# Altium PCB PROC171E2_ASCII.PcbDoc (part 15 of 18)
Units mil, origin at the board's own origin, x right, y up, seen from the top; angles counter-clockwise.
Board outline 7700 x 2300 mil, 6 copper layers (Top Layer, GND 1, SIG 1, SIG 2, GND 2, Bottom Layer), stack 61.062 mil thick; 938 components, 688 nets, 11933 pads, 1723 vias.
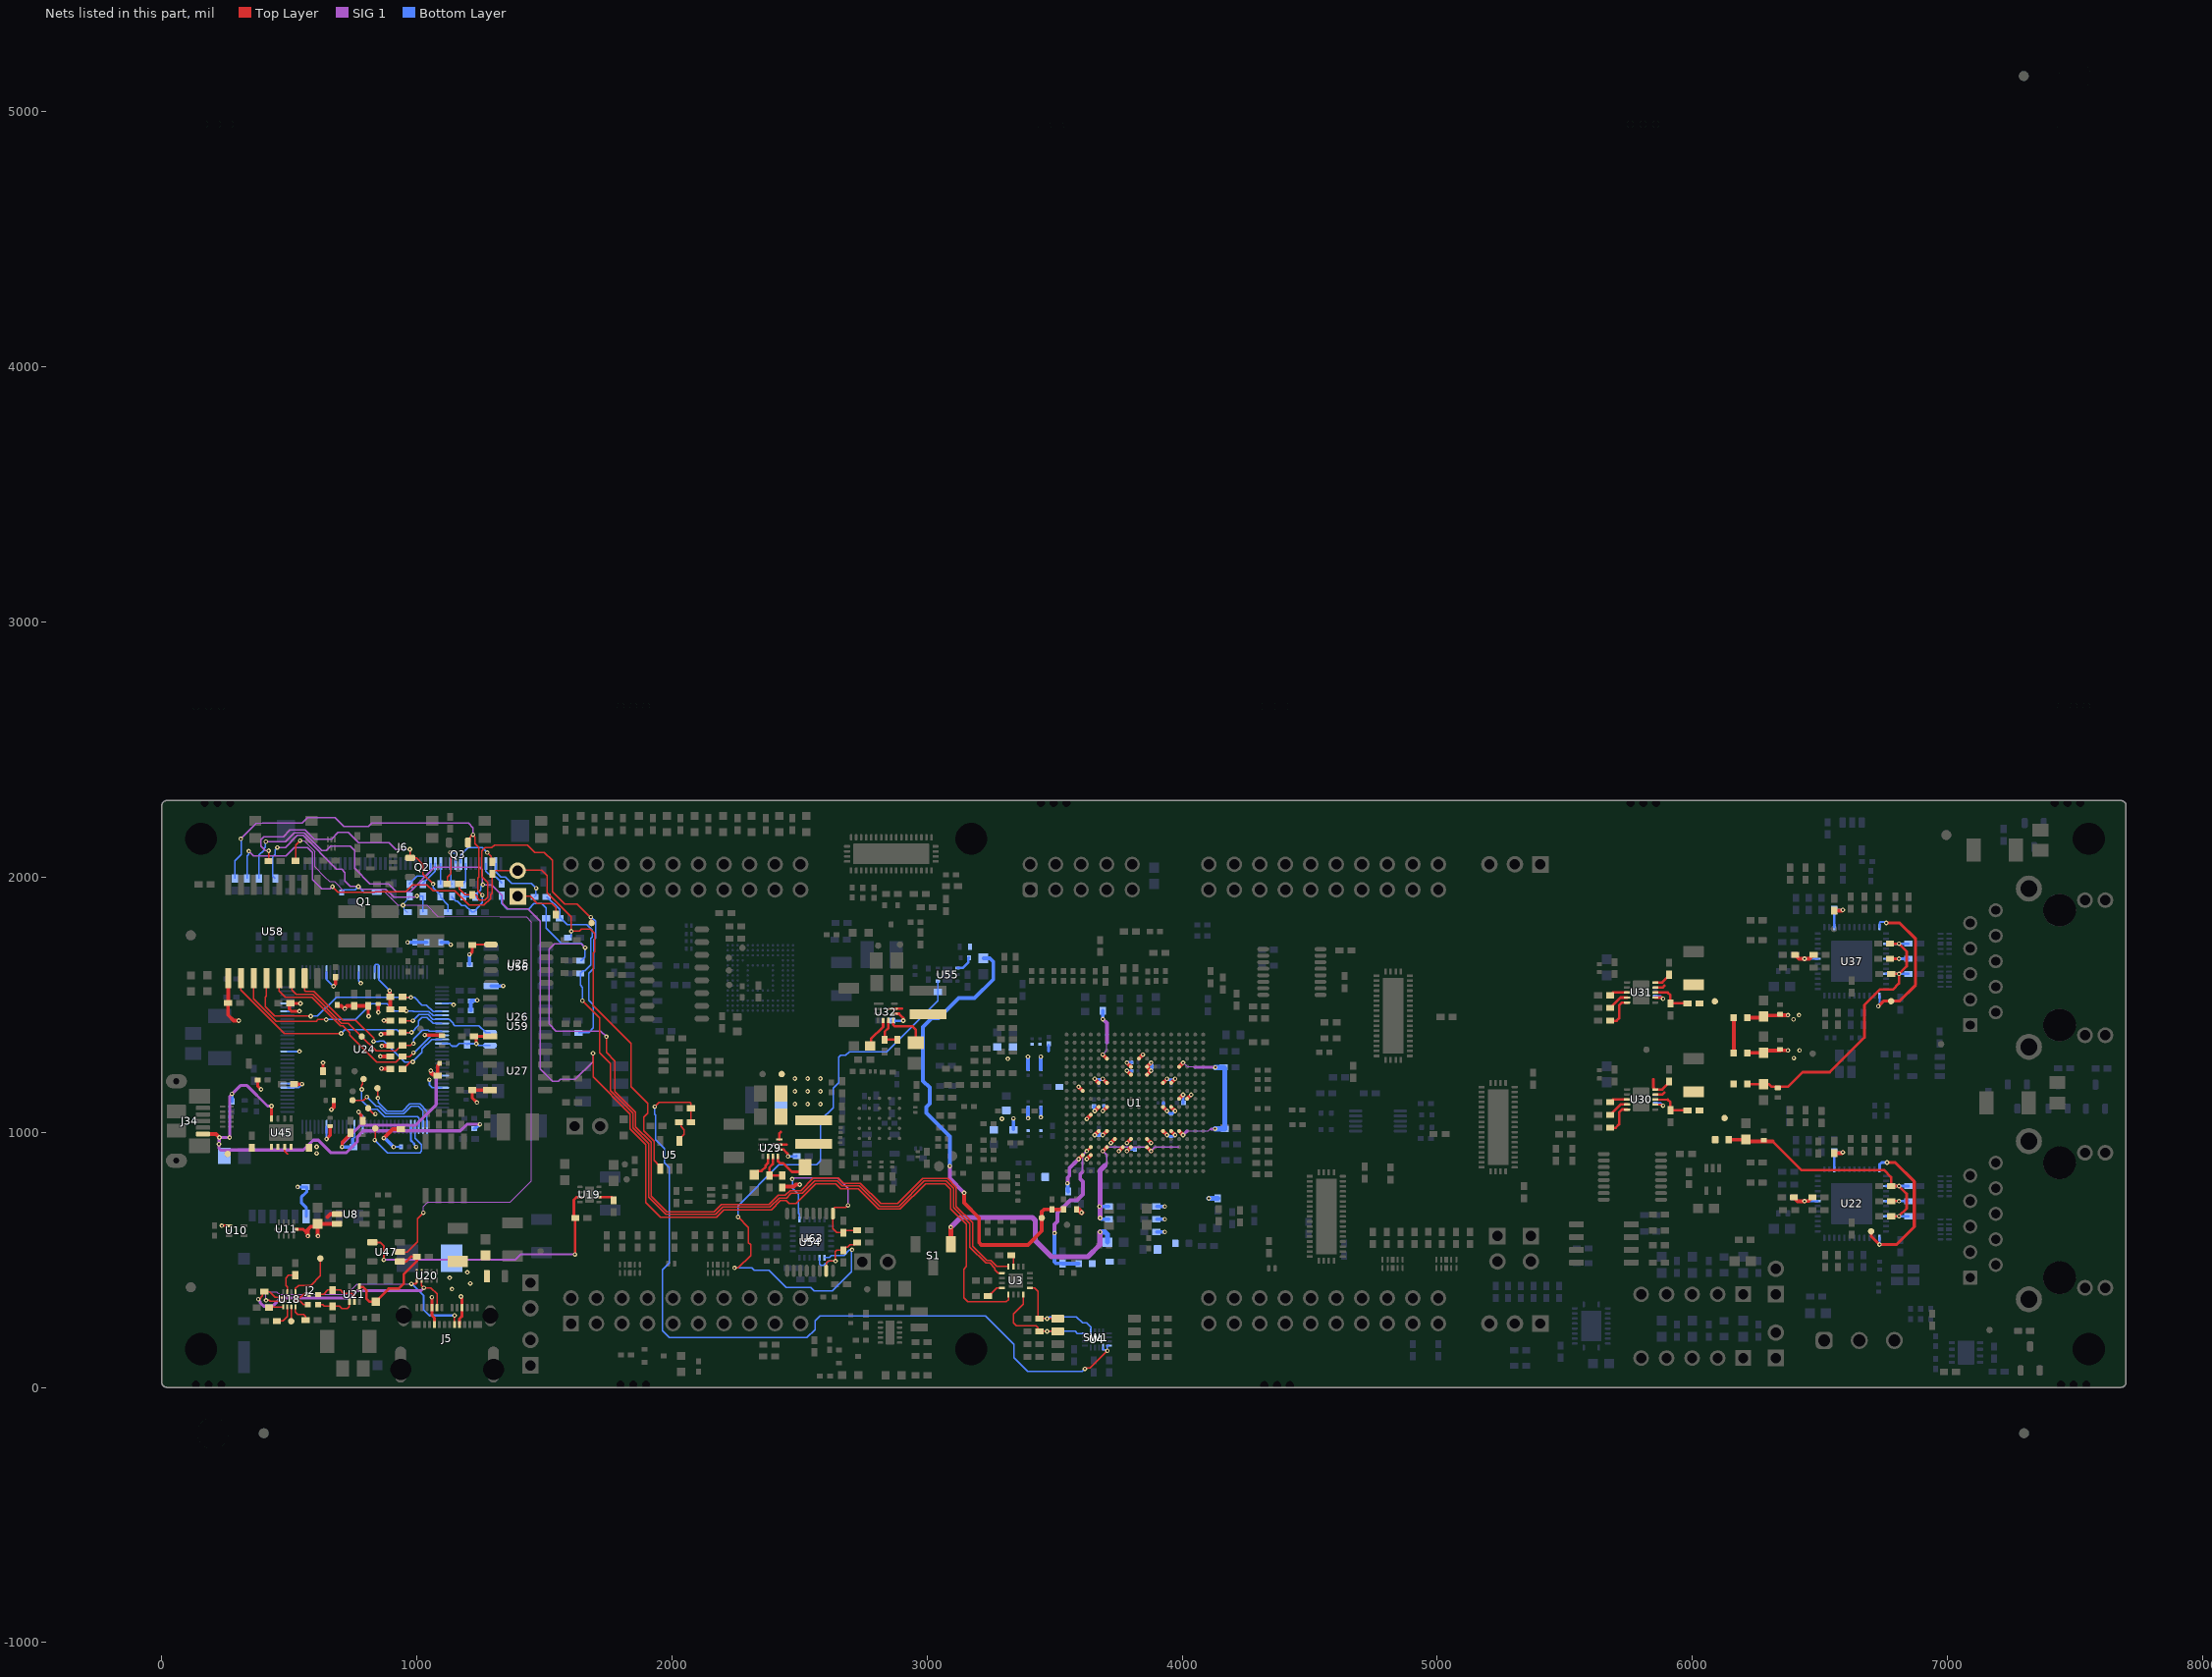
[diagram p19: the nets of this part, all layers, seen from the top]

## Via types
v1: diameter 18, hole 8, Top Layer to Bottom Layer, tented both sides, 1592 vias
v2: diameter 19.68, hole 7.87, Top Layer to Bottom Layer, tented both sides, 104 vias
v3: diameter 19.68, hole 7.87, Top Layer to Bottom Layer, 24 vias
v4: diameter 18, hole 8, Top Layer to Bottom Layer, 3 vias

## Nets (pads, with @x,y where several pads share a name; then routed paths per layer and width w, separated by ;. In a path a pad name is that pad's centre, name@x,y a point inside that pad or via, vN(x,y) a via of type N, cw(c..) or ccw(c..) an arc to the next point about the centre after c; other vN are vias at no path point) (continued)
SOP2_SW: R16.2 SW1.6 U3.4 U4.8 | length 476.2
  Top Layer w5.3: U3.4@3377.58,363.58 3377.58,327.08 3338.08,287.58 3338.08,252.82 3349.82,241.09 3353.63,241.09 3353.88,240.83 3370.06,240.83 3370.88,241.65 3427.87,241.65 3435.55,233.97 3435.55,219.51 v1(3470.3,219.51) SW1.6@3512.3,219.51
  Bottom Layer w5.3: v1(3470.3,219.51) 3581.42,219.51 3589.52,211.4 U4.8@3618.83,211.4
SOP3_SW: R17.2 SW1.5 U3.5 U4.9 | length 429.8
  Top Layer w5.3: U3.5@3403.17,389.17 3422,389.17 3435.55,375.62 3435.55,269.51 v1(3470.3,269.51) SW1.5@3512.3,269.51
  Bottom Layer w5.3: v1(3470.3,269.51) 3472.41,269.51 3479.75,276.85 3585.81,276.85 3610.21,252.45 3626.12,252.45 3642.45,236.12 U4.9@3642.45,219.28
SOP_DRIVE_OEN_R: R18.1 U5.4 | length 88.4
  Top Layer w5.3: U5.4@2028.71,965.53 2028.71,973.41 2047.77,992.46 2047.77,1010.18 2035.53,1022.42 2035.53,1034.66 R18.1@2031.05,1039.14
SOP_DRIVER_OEN: R18.2 R20.1 U4.1 U4.16 | length 3144.1
  Top Layer w5.3: v1(1932.26,1100.31) 1948.94,1116.99 2071.32,1116.99 2074.43,1113.89 R18.2@2074.43,1039.07 ; v1(3618.62,72.77) 3621.05,75.2 3638.62,75.2 v1(3706.65,143.24)
  Bottom Layer w5.3: v1(1932.26,1100.31) 1932.26,1070.44 1936.08,1066.62 1936.08,970.24 1970.28,936.04 1970.28,880.37 1989.78,860.87 1989.78,487.27 1963.14,460.63 1963.14,221.49 1990.23,194.4 2528.89,194.4 2561.1,226.61 2561.1,260.35 2580.86,280.11 3086.76,280.11 3086.8,280.15 3228.84,280.15 3340.56,168.43 3340.56,116.68 3395.19,62.05 3607.89,62.05 v1(3618.62,72.77) ; U4.1@3689.69,158.25 3689.69,148.41 3690.98,147.12 v1@3699.33,147.12 ; v1@3706.65,149.1 3706.65,162.87 3707.94,164.16 U4.16@3713.32,164.16
TA_GPIO1: Q3.1 R185.2 R342.2 R350.1 | length 1656.9
  Top Layer w5.3: Q3.1@1200.4,2131.24 1207.55,2138.4 1207.55,2156.55 1217,2166 v1(1220,2166) 1220,2164.37 1227.83,2156.55 1227.83,2130.72 1243.4,2115.15 1243.4,2000.59 1239.14,1996.33 1239.14,1947.32 v1(1257.17,1929.29)
  SIG 1 w5.3: v1(309.92,2150.15) 369.84,2210.07 395.43,2211.24 396.69,2211.3 396.91,2211.52 412.09,2211.52 ; 412.13,2211.52 538.8,2212.58 ; 538.85,2212.58 551,2212.58 572.42,2234 679,2234 713.7,2199.3 810.49,2199.3 822.82,2211.63 1201.87,2211.63 1220,2193.49 v1(1220,2166)
  Bottom Layer w5.3: R342.2@287,1994.62 287,2064 311,2088 v1@311,2149 ; R350.1@1138.11,1924.76 1138.11,1920.82 1152.93,1906 1158.27,1906 1160.43,1903.85 1174.97,1889.3 1189.9,1889.3 1216.26,1862.94 R185.2@1220.2,1862.94 1224.13,1862.94 1233.3,1872.1 1233.3,1876.04 1257.17,1899.91 v1(1257.17,1929.29)
TA_GPIO1_R: J6.30 R350.2 | length 83.6
  Bottom Layer w5.3: J6.30@1132.64,2053.35 1132.64,1977.47 R350.2@1138.11,1972
TA_GPIO1_XDS: R341.2 U24.74 U58.2 | length 997.1
  Top Layer w5.3: U58.2@310.25,1603.6 310.25,1557.91 480.85,1387.32 v1(703.3,1387.32) ; R341.2@943.31,1390.96 v1(979.22,1390.96)
  Bottom Layer w5.3: v1(703.3,1387.32) 718.75,1402.77 921.32,1402.77 933.13,1390.96 v1(979.22,1390.96) 1007.06,1418.8 1007.06,1437.32 1020,1450.26 1039.87,1450.26 1063.4,1426.73 U24.74@1098.65,1426.73
TA_GPIO2: R184.2 R351.1 R359.2 TP18.1 | length 1529
  Top Layer w5.3: R351.1@1166.36,1973.49 1166.36,1953.41 1189.34,1930.42 R184.2@1216.66,1930.42 1232.5,1930.42 1237.64,1925.28 1237.64,1917.62 1245.49,1909.77 1267.07,1909.77 1278.45,1921.14 1278.45,1978.55 1254,2003 1254,2101.61 1267.91,2115.52 1293.52,2115.52 1304,2126 1434,2126 1463,2097 1500,2097 1531,2066 1531,1943 1579.9,1894.1 1627.88,1894.1 1679.09,1842.89 v1(1681.82,1842.89) 1683.41,1841.29 1683.41,1821.59 TP18.1@1685,1820
  Bottom Layer w5.3: R359.2@1633.91,1389.97 1673.34,1389.97 1692.16,1408.79 1692.16,1437.84 1692.15,1500.55 1674.95,1517.75 1674.95,1623.27 1693.26,1641.58 1693.26,1754.66 1701,1762.4 1701,1826.2 1684.32,1842.89 v1(1681.82,1842.89)
TA_GPIO2_R: J6.31 R351.2 | length 192.6
  Top Layer w5.3: R351.2@1119.11,1973.49 1119.11,2000.89 1132.94,2014.72 1132.94,2095.06 v1(1131,2097)
  Bottom Layer w5.3: v1(1131,2097) 1133.43,2094.57 1149.77,2094.57 1152.87,2091.47 1152.87,2053.9 J6.31@1152.32,2053.35
TA_GPIO2_XDS: R301.2 U24.73 U59.2 | length 385.5
  Top Layer w5.3: R301.2@943.31,1437.81 944.33,1436.79 v1(984.31,1436.79)
  Bottom Layer w5.3: v1(984.31,1436.79) 1008.38,1460.86 1044.26,1460.86 1062.65,1442.48 U24.73@1098.65,1442.48 1099.14,1441.99 1127.95,1441.99 1142.66,1427.28 1142.66,1423.59 1148.55,1417.7 1243.5,1417.7 1271.2,1390 U59.2@1286.89,1390
TA_GPIO3: J1.2 R183.2 R343.2 R352.1 U5.1 | length 3033
  Top Layer w5.3: v1(669.14,1962.79) 669.86,1962.79 691.08,1941.58 834.88,1941.58 835.28,1941.98 956.39,1941.98 983.93,1969.52 1039.51,1969.52 1063.36,1945.67 1148.59,1945.67 1204,1890.25 1262.85,1890.25 1289.05,1916.45 1289.05,1931.74 1294.15,1936.85 1294.15,2010.53 R352.1@1296,2012.38 1296,2015.84 1305.16,2025 J1.2@1395.54,2025 ; J1.2@1398,2025 1400.3,2027.3 1488.7,2027.3 1510.7,2005.3 1510.7,1937.82 1604.02,1844.5 1604.02,1789.16 v1(1605.23,1787.95) ; v1@1604.76,1788.41 1637.55,1788.41 1645.13,1796 1680.12,1796 1696.34,1779.78 1696.34,1708.55 1690.74,1702.96 1690.74,1497.06 1839.67,1348.13 1839.67,1179.54 1906.02,1113.19 1906.02,1075.61 1889.8,1059.39 1889.8,1004.74 1929.68,964.87 1929.68,889.37 1953.91,865.14 U5.1@1953.91,857.27
  SIG 1 w5.3: v1(341,2102) 359.52,2083.48 486.48,2083.48 518.82,2115.82 571.75,2115.82 590.67,2096.9 590.67,1991.22 627.7,1954.18 659.31,1954.18 667.92,1962.79 v1(669.14,1962.79)
  Bottom Layer w5.3: R343.2@334.13,1994.62 334.13,2082.13 340.81,2088.81 340.81,2101.81 v1(341,2102) ; R183.2@1603.77,1765 1605.23,1766.46 v1(1605.23,1787.95)
TA_GPIO3_PD: J1.1 R21.2 | length 195.5
  Top Layer w5.3: J1.1@1395.54,1925 1444.27,1925 1473.05,1896.23 1529.94,1896.23 1545,1881.17 R21.2@1545,1853.25
TA_GPIO3_R: J6.32 R352.2 | length 201.6
  Top Layer w5.3: v1(1276,2096) 1291.78,2080.22 1291.78,2063.84 R352.2@1296,2059.62
  Bottom Layer w5.3: J6.32@1172.01,2053.35 1172.47,2053.81 1172.47,2086.47 1201.46,2115.46 1256.54,2115.46 v1(1276,2096)
TA_GPIO3_XDS: R340.2 U24.72 U58.3 | length 920.3
  Top Layer w5.3: U58.3@360.25,1603.6 360.25,1522.91 447.68,1435.48 605.4,1435.48 611.43,1441.5 v1(644.66,1441.5) ; R340.2@943.31,1481.93 951.93,1481.93 v1(958.55,1475.32)
  Bottom Layer w5.3: v1(644.66,1441.5) 760.46,1441.5 822.55,1503.59 884.17,1503.59 912.45,1475.32 v1(958.55,1475.32) 986.1,1475.32 987.65,1473.77 1047.7,1473.77 1063.24,1458.23 U24.72@1098.65,1458.23
TA_GPIO4: R182.2 R344.2 R354.1 U3.1 | length 5252
  Top Layer w5.3: v1(1690.74,1309.56) 1690.74,1216.22 1836.74,1070.21 1836.74,1012.83 1897.88,951.7 1897.88,724.83 1955.31,667.4 2174.55,667.4 2203.31,696.16 2389.14,696.16 2425.13,732.14 2448.04,732.14 2459.62,720.56 2485.61,720.56 2563.24,798.19 2642.28,798.19 2661.41,779.07 2730.19,779.07 2809.98,699.28 2895.07,699.28 2993.41,797.62 3071.26,797.62 3093.09,775.78 3093.09,700.37 3154.53,638.93 3154.53,473.86 3144.05,463.38 3144.05,351 3160.02,335.03 3310.03,335.03 3318.53,343.53 U3.1@3318.53,363.58
  SIG 1 w5.3: v1@410,2138 485,2138 520.53,2173.53 558.23,2173.53 627.58,2104.19 645.19,2104.19 662,2121 739.61,2121 756,2104.61 756,2034.1 815.83,1974.27 888.73,1974.27 920,1943 973,1943 1068.42,2038.42 1247.4,2038.42 1257.17,2028.65 1257.17,1971.95 v1(1258.92,1970.19) ; v1@1259.42,1970.19 1292.52,1970.19 1336.26,1926.46 1336.26,1895.72 1356.8,1875.17 1435.31,1875.17 1482.95,1827.52 1482.95,1248.59 1531.98,1199.56 1555.79,1199.56 1563.23,1207 1620.77,1207 1690.74,1276.97 v1(1690.74,1309.56)
  Bottom Layer w5.3: R344.2@381.31,1994.9 381.31,2086.31 399.48,2104.48 399.48,2111.09 406,2117.61 406,2137 v1(408,2139) ; R354.1@1182.29,1923.75 1228.05,1923.75 R182.2@1228.48,1923.32 1237.64,1932.48 1237.64,1937.95 1250.34,1950.65 1250.34,1961.61 v1(1258.92,1970.19)
TA_GPIO4_R: J6.33 R354.2 | length 86.2
  Bottom Layer w5.3: R354.2@1182.29,1971 1182.29,1974.93 1191.69,1984.34 J6.33@1191.69,2053.35
TA_GPIO4_XDS: R339.2 U24.71 U58.4 | length 908.9
  Top Layer w5.3: U58.4@410.25,1603.6 410.25,1534.58 405.26,1529.58 405.26,1492.89 443.15,1455 v1(584.18,1455) ; R339.2@943.31,1530.84 945.45,1528.69 v1(976.28,1528.69)
  Bottom Layer w5.3: v1(584.18,1455) 610.75,1455 684.44,1528.69 990.39,1528.69 1020.07,1499.02 1038.2,1499.02 1063.24,1473.98 U24.71@1098.65,1473.98
TA_I2C_SCL: R191.1 R356.1 R411.2 U3.12 | length 3748.3
  Top Layer w5.3: v1(1742.84,1374.31) 1742.84,1313.39 1776.91,1279.32 1776.91,1160.02 1857.94,1079 1857.94,1021.61 1919.08,960.48 1919.08,749.65 1980.13,688.6 2165.77,688.6 2194.53,717.36 2380.36,717.36 2416.35,753.34 2444.39,753.34 2462.45,771.41 2501.24,771.41 2505.35,771.41 2554,820.06 2652.61,820.06 2672.4,800.27 2738.97,800.27 2818.76,720.48 2883.63,720.48 2981.97,818.82 3080.04,818.82 3114.29,784.57 3114.29,709.15 3178.1,645.34 3178.1,554.05 3234.61,497.54 3250.35,497.54 3274.08,473.82 U3.12@3318.53,473.82
  SIG 1 w5.3: v1(1659.51,1723.8) 1644.52,1738.8 1539.94,1738.8 1517.66,1716.52 1517.66,1424.19 1545.3,1396.55 1720.59,1396.55 v1(1742.84,1374.31)
  Bottom Layer w5.3: R356.1@1331.93,1927.43 1331.93,1897.51 1353.49,1875.95 1438.86,1875.95 1459.13,1896.23 1490.16,1896.23 1507,1879.39 R191.1@1507,1838.89 1507,1800 1566.86,1740.14 1643.18,1740.14 v1(1659.51,1723.8) 1659.51,1686.92 1645.43,1672.84 R411.2@1641.49,1672.84
TA_I2C_SCL_R: J6.37 R356.2 | length 113.4
  Bottom Layer w5.3: J6.37@1270.43,2053.35 1270.43,2024.27 1294.23,2000.47 1310.07,2000.47 1331.93,1978.61 R356.2@1331.93,1974.68
TA_I2C_SDA: R192.1 R358.1 R409.2 U3.13 | length 3235.8
  Top Layer w5.3: v1(1649.12,1515.38) 1716.8,1447.7 1716.8,1311.11 1759.04,1268.88 1759.04,1162.91 1847.34,1074.61 1847.34,1017.22 1908.48,956.09 1908.48,745.26 1975.74,678 2170.16,678 2198.92,706.76 2384.75,706.76 2420.74,742.74 2448.78,742.74 2463.04,757.01 2466.84,760.81 2510.87,760.81 2559.52,809.46 2647.76,809.46 2667.55,789.67 2734.58,789.67 2814.37,709.88 2890.68,709.88 2989.02,808.22 3075.65,808.22 3103.69,780.17 3103.69,704.76 3167.5,640.94 3167.5,549.66 3230.22,486.94 3245.96,486.94 3266.36,466.54 3266.36,460.34 3278.47,448.23 U3.13@3292.94,448.23
  Bottom Layer w5.3: R358.1@1509.01,1923.75 1559.77,1873 R192.1@1559.77,1838.79 1563.7,1838.79 1588.88,1813.62 1666.93,1813.62 1688.52,1792.03 1688.52,1764.91 1682.66,1759.05 1682.66,1655.31 1659.25,1631.89 1650.19,1631.89 R409.2@1641.03,1622.73 1641.03,1576.31 1649.12,1568.22 v1(1649.12,1515.38)
TA_I2C_SDA_R: J6.39 R358.2 | length 252.3
  Bottom Layer w5.3: J6.39@1309.8,2053.35 1309.8,2020.08 1329.41,2000.47 1347.91,2000.47 1372.89,1975.5 1449.08,1975.5 v1@1466.29,1958.29 ; R358.2@1461.38,1923 1466,1927.62 v1@1466,1958
  other v1: 1468.12,1956.46
TA_PORZ: Q1.1 R180.1 R187.2 R345.2 R347.1 | length 1067.8
  SIG 1 w5.3: v1@454,2115 484,2115 531.93,2162.93 553.84,2162.93 685.77,2031 705.7,2031 718.24,2018.47 718.24,1984.67 739.91,1963 v1(771,1963) 780.93,1953.07 877.93,1953.07 910,1921 991.91,1921 996.99,1926.07 v1(1000.42,1926.07)
  Bottom Layer w5.3: R345.2@445,1994.62 435.84,2003.78 435.84,2009.99 435,2010.82 435,2080.39 444,2089.39 444,2106.55 453,2115.55 v1(453,2116) ; R180.1@706,1940.32 706,1942.28 713.19,1949.48 757.48,1949.48 v1(771,1963) 792.48,1941.52 Q1.1@842.87,1941.52 ; R180.1@706.82,1937.79 R180.1@706.82,1939.76 ; v1(1000.42,1926.07) 1003.62,1926.07 1006.59,1923.11 1008.24,1924.76 R347.1@1024.02,1924.76 1024.02,1864.97 R187.2@1026.05,1862.94
TA_PORZ_R: J6.27 R347.2 | length 101.9
  Bottom Layer w5.3: R347.2@1024.02,1972 1024.02,1975.94 1072.01,2023.93 1072.01,2051.77 J6.27@1073.58,2053.35
TA_PORZn_XDS: R338.2 U24.77 U58.5 | length 852.1
  Top Layer w5.3: U58.5@460.25,1603.6 460.25,1554.54 485.54,1529.25 588.68,1529.25 700.83,1417.11 709.49,1417.11 736.59,1390.01 736.59,1381.08 842.97,1274.7 917.51,1274.7 939.37,1296.56 R338.2@943.31,1296.56 971.67,1296.56 986.6,1311.49 v1(986.6,1311.61)
  Bottom Layer w5.3: v1(986.6,1311.61) 989.67,1311.61 1057.05,1379 1098.16,1379 U24.77@1098.65,1379.49
TA_POWERDOWNZ: R188.2 R346.1 R353.2 U47.2 | length 2953.3
  Top Layer w5.3: R353.2@524.76,2064 524.76,2125.76 v1@541.85,2142.85 ; U47.2@933.63,531 962.79,531 1002.6,570.81 1002.6,661.18 v1(1025.82,684.4)
  SIG 1 w4.75: v1@541.91,2143.41 v1(542.32,2143) v1@543,2143 ; v1@543,2143.41 558.76,2143.41 600.99,2101.18 600.99,2041.05 637.7,2003 658.05,1982.65 676.5,1982.65 716.41,1942.74 873.26,1942.74 926.25,1889.75 v1(945.6,1889.75) ; v1@948.76,1889.75 1039.1,1889.75 1082.45,1846.39 1326.11,1843.51 ccw(c1326.34,1862.76) 1326.59,1843.51 1424.3,1845 1428.24,1845 1429.63,1843.61 1449.33,1823.91 1449.33,1121.99 ; v1(1025.82,684.4) 1025.82,708.65 1043,725.82 1366.23,725.82 1449.32,808.92 1449.32,1121.98
  Bottom Layer w4.75: R188.2@963.89,1862.94 959.96,1862.94 950.52,1872.37 950.52,1881.24 945.6,1886.16 v1(945.6,1889.75) 948.14,1892.29 948.14,1897.22 971.74,1920.82 R346.1@971.74,1924.76
TA_POWERDOWNZ_R: J6.26 R346.2 | length 136
  Bottom Layer w5.3: R346.2@971.74,1972 971.74,1975.94 999.94,2004.14 1035.15,2004.14 1053.9,2022.88 J6.26@1053.9,2053.35
TA_PWRDNz_XDS: R336.2 U24.78 U58.7 | length 810.5
  Top Layer w5.3: U58.7@560.25,1603.6 560.25,1554.96 563.36,1551.86 596.06,1551.86 709.61,1438.31 760.87,1438.31 830.55,1368.63 v1(830.55,1356.24) ; R336.2@943.31,1248.06 947.24,1248.06 975.17,1275.98 984.23,1275.98 v1(984.54,1275.67)
  Bottom Layer w5.3: v1(830.55,1356.24) 831.96,1354.83 850.15,1354.83 853.03,1357.71 870.6,1357.71 952.65,1275.67 v1(984.54,1275.67) ; v1(984.54,1275.67) 984.51,1278.25 1019.82,1313.56 1019.82,1325.87 1057.69,1363.74 U24.78@1098.65,1363.74
TA_RESETZ: Q2.1 R186.2 R348.1 R349.2 | length 1076.7
  Top Layer w5.3: R349.2@418.76,2063 418.76,2102.76 v1(419,2103) ; v1(973,2109) 973.76,2108.24 Q2.1@973.76,2075.4 ; Q2.1@975,2075 999,2075 1024.64,2049.36 1024.64,2012 v1(1063.57,1973.07)
  SIG 1 w5.3: v1(419,2103) 418.31,2103.69 406.31,2103.69 388.48,2121.52 388.48,2147.09 399.91,2158.52 477.52,2158.52 503.13,2184.13 562.62,2184.13 597.75,2149 664.95,2149 690.47,2174.52 731.48,2174.52 771,2135 891,2135 917,2109 v1(973,2109)
  Bottom Layer w5.3: v1(1063.57,1973.07) 1063.57,1957.38 1092.26,1928.7 R348.1@1092.26,1924.76 1092.26,1920.82 1121.59,1891.49 R186.2@1121.59,1862.94
TA_RESETZ_R: J6.28 R348.2 | length 81.8
  Bottom Layer w5.3: R348.2@1092.26,1972 1093.27,1973.01 J6.28@1093.27,2053.35
TA_RESETz_XDS: R337.2 TP32.1 U24.76 U58.6 | length 779.8
  Top Layer w5.3: U58.6@510.25,1603.6 510.25,1557.01 527.42,1539.85 593.07,1539.85 705.22,1427.71 731.47,1427.71 TP32.1@784.17,1375 840.51,1318.67 917.51,1318.67 939.37,1340.53 R337.2@943.31,1340.53 976.2,1340.53 983.28,1347.61 v1(986.59,1347.61)
  Bottom Layer w5.3: v1(986.59,1347.61) 986.59,1364.76 1022.23,1400.4 1044.54,1400.4 1049.71,1395.24 U24.76@1098.65,1395.24
TCA_ADDR: R10.2 U3.16 | length 67
  Top Layer w5.3: R10.2@3238.62,358.58 3247.78,367.74 3252.17,367.74 3273.6,389.17 U3.16@3292.94,389.17
TCA_INTN: R11.2 U3.11 | length 46.5
  Top Layer w5.3: R11.2@3330.46,517.07 3338.21,509.32 U3.11@3338.21,473.82
TM4C129_TCK: TP27.1 U24.100 | length 359.1
  Top Layer w5.3: v1(834.93,969.22) 836.15,970.44 836.15,1013.78 TP27.1@837.37,1015
  Bottom Layer w5.3: v1(834.93,969.22) 884.44,919.71 1011.99,919.71 1018.05,925.76 1018.05,950.75 992.31,976.49 992.31,1021.18 U24.100@992.35,1021.22
TM4C129_TDI: TP29.1 U24.98 | length 389.7
  Top Layer w5.3: TP29.1@747.83,1125.66 791.27,1125.66 v1(803.8,1138.19)
  Bottom Layer w5.3: v1(803.8,1138.19) 840.65,1101.33 849.78,1101.33 878.6,1072.51 948.54,1072.51 976.75,1100.72 1007,1100.72 1023.85,1083.87 U24.98@1023.85,1021.22
TM4C129_TDO: TP30.1 U24.97 | length 347
  Top Layer w5.3: TP30.1@845.57,1172.78 846.44,1171.91 846.44,1135.02 v1(847.31,1134.15)
  Bottom Layer w5.3: v1(847.31,1134.15) 848.91,1132.55 848.91,1117.2 882.99,1083.11 944.15,1083.11 972.36,1111.32 1011.39,1111.32 1039.59,1083.11 U24.97@1039.59,1021.22
TM4C129_TMS: TP28.1 U24.99 | length 373
  Top Layer w5.3: v1(784.17,1168.37) 784.17,1185.32 787.4,1188.54 787.4,1204.77 TP28.1@791.17,1208.54
  Bottom Layer w5.3: v1(784.17,1168.37) 784.17,1125.66 819.11,1090.73 845.39,1090.73 856.83,1079.29 874.45,1061.67 1001.81,1061.67 1008.1,1055.38 U24.99@1008.1,1021.22
TPS62913_1_EN_SYNC: R146.1 U29.1 | length 85.6
  Top Layer w10: U29.1@2420.33,931.84 2438.13,931.84 2453.47,916.5 2453.47,906.8 v1(2455,905.27)
  Bottom Layer w10: v1(2455,905.27) 2455.71,905.98 2488,905.98 R146.1@2488.71,906.68
TPS62913_1_FB: R153.1 R154.2 U29.9 | length 130.5
  Top Layer w10: U29.9@2395.73,905.26 2395.73,874.96 2382.33,861.57 R154.2@2382.33,830.3 R153.1@2432.33,830.3
TPS62913_1_NR_SS: C160.1 U29.8 | length 102.5
  Top Layer w10: C160.1@2322.84,833.18 2322.84,834.16 2336.54,847.86 2350.85,847.86 2367.03,864.05 2367.03,870.42 2376.04,879.44 U29.8@2376.04,905.26
TPS62913_1_SCONF: R148.2 U29.10 | length 127.9
  Top Layer w10: U29.10@2415.41,905.26 2415.41,886.62 2423.84,878.19 2436.49,878.19 2470,844.68 R148.2@2507.33,844.68
TPS62913_1_SW: L2.1 U29.2 | length 36.6
  Top Layer w10: U29.2@2413.45,951.52 2450,951.52
TPS62913_2_EN_SYNC: R156.1 U32.1 | length 95.8
  Top Layer w10: U32.1@2872.01,1464.46 2889.83,1464.46 2906.67,1447.62 v1(2906.67,1437.62)
  Bottom Layer w10: R156.1@2861.31,1436.47 v1@2905.52,1436.47
TPS62913_2_FB: R162.1 R163.2 U32.9 | length 130.5
  Top Layer w10: U32.9@2847.4,1437.88 2847.4,1407.58 2834,1394.19 R163.2@2834,1362.92 R162.1@2884,1362.92
TPS62913_2_NR_SS: C177.1 U32.8 | length 121
  Top Layer w10: C177.1@2776.59,1338.05 2780.43,1341.89 2780.43,1365.89 2827.72,1413.18 U32.8@2827.72,1437.88
TPS62913_2_SCONF: R160.2 U32.10 | length 164.5
  Top Layer w10: U32.10@2867.09,1437.88 2867.09,1422.06 2874.55,1414.59 2943.56,1414.59 2956.47,1401.68 R160.2@2956.47,1350.85
TPS62913_2_SW: L3.1 U32.2 | length 36.6
  Top Layer w10: U32.2@2865.12,1484.14 2901.67,1484.14
TPS74801_1_BIAS: R150.2 U30.4 | length 83.3
  Top Layer w10: R150.2@5677.75,1067.63 5718.86,1108.75 U30.4@5744.01,1108.75
TPS74801_1_EN: R149.2 U30.5 | length 123.2
  Top Layer w10: R149.2@5677.75,1017.63 5699.82,1017.63 5712.84,1030.65 5712.84,1077.3 5724.6,1089.06 U30.5@5744.01,1089.06
TPS74801_1_FB: R151.1 R152.2 U30.8 | length 162.4
  Top Layer w8: U30.8@5854.25,1128.43 5903.33,1128.43
  Top Layer w10: 5903.33,1128.43 5914.13,1117.63 R152.2@5914.13,1085.98 R151.1@5980.51,1085.98
TPS74801_1_PG: R147.1 U30.3 | length 70.7
  Top Layer w10: R147.1@5677.75,1117.63 5688.55,1128.43 U30.3@5744.01,1128.43
TPS74801_1_SS: C166.2 U30.7 | length 68.3
  Top Layer w8: U30.7@5854.25,1108.75 5877.91,1108.75 v1@5883.57,1103.09
  Top Layer w10: v1@5882.84,1103.83 v1(5885,1103.83)
  Bottom Layer w10: C166.2@5854.25,1112.69 5875.45,1112.69 5884.3,1103.83 v1(5885,1103.83)
TPS74801_2_BIAS: R158.2 U31.4 | length 83.3
  Top Layer w10: R158.2@5677.75,1486.82 5718.86,1527.94 U31.4@5744.01,1527.94
TPS74801_2_EN: R157.2 U31.5 | length 125.2
  Top Layer w10: R157.2@5677.75,1436.82 5703.29,1436.82 5712.84,1446.37 5712.84,1496.49 5724.6,1508.25 U31.5@5744.01,1508.25
TPS74801_2_FB: R159.1 R161.2 U31.8 | length 162.4
  Top Layer w10: U31.8@5854.25,1547.62 5903.33,1547.62 5914.13,1536.82 R161.2@5914.13,1505.17 R159.1@5980.51,1505.17
TPS74801_2_PG: R155.1 U31.3 | length 70.7
  Top Layer w10: R155.1@5677.75,1536.82 5688.55,1547.62 U31.3@5744.01,1547.62
TPS74801_2_SS: C178.2 U31.7 | length 67.2
  Top Layer w10: U31.7@5854.25,1527.94 5880.08,1527.94 v1(5885,1523.02)
  Bottom Layer w10: C178.2@5854.25,1531.87 5875.45,1531.87 5884.3,1523.02 v1(5885,1523.02)
TPS_CT: C109.1 U19.6 | length 64.7
  Top Layer w10: U19.6@1714.33,746.06 1763.07,746.06 1771.58,737.56 C109.1@1771.58,733.62
TPS_VSYS_5V0_ON: R98.1 U19.3 U47.4 | length 1108.3
  Top Layer w8: U47.4@825.37,568.4 856.6,568.4 870,555 v1(870,499.73)
  Top Layer w10: v1(1620,520.76) 1620,664.65 1615.61,669.04 1615.61,734.29 1627.39,746.06 U19.3@1639.52,746.06
  SIG 1 w8: v1(870,499.73) 1384.73,499.73 1405.76,520.76 v1(1620,520.76)
TUSB_ADDR: TP5.1 U18.5 | length 56.5
  Top Layer w5.3: TP5.1@507.51,259.31 508.07,259.87 U18.5@508.07,315.56
TUSB_EN_N: R97.2 U18.11 | length 98.2
  Top Layer w5.3: U18.11@492.32,374.61 492.24,374.69 492.24,393.2 486.21,399.23 486.21,428.62 497.39,439.79 R97.2@523.29,439.79
TUSB_ID: TP3.1 U18.9 | length 199.6
  Top Layer w5.3: U18.9@523.82,374.61 523.9,374.69 523.9,387.72 536.18,400 584.4,400 621.55,437.15 TP3.1@621.55,505.45
TUSB_OUT: DS4.1 R299.1 U21.4 U47.1 | length 447.5
  Top Layer w10: U21.4@774.98,394.13 788.32,394.13 801.98,380.48 801.98,347.94 814.26,335.65 DS4.1@838.68,335.65 890.03,387 929,387 948,406 948,442.5 999.88,494.38 R299.1@999.88,512.5 977.5,512.5 958.6,493.6 U47.1@933.63,493.6
TUSB_OUT1: R89.2 R93.2 U21.1 | length 152.9
  Top Layer w5.3: R89.2@612.51,324.31 630.69,324.31 637.07,317.93 R93.2@669.95,317.93 696.07,317.93 705.97,308.03 727.47,308.03 735.61,316.17 U21.1@735.61,335.87
TUSB_OUT1_R: R89.1 U18.7 | length 52.7
  Top Layer w5.3: U18.7@525.79,337.21 543.62,337.21 556.48,324.35 R89.1@573.14,324.31 R89.1@573.14,324.31
TUSB_OUT2: R90.2 R92.2 U21.2 | length 181.4
  Top Layer w5.3: R90.2@612.51,364.41 634.16,364.41 650.82,381.07 R92.2@669.95,381.07 700,381.07 712.8,368.26 745,368.26 755.3,357.97 U21.2@755.3,335.87
TUSB_OUT2_R: R90.1 U18.8 | length 52.1
  Top Layer w5.3: U18.8@525.79,352.96 544.38,352.96 555.83,364.41 R90.1@573.14,364.41
TUSB_OUT3: R91.1 U18.6 | length 81.7
  Top Layer w5.3: U18.6@523.82,315.56 523.82,295 533.82,285 556.48,285 563.88,277.6 R91.1@563.88,263.69
TUSB_PORT: R95.2 U18.3 | length 57.8
  Top Layer w5.3: R95.2@420.03,312.6 422.98,315.56 U18.3@476.58,315.56
TUSB_VBUS_DET: R94.1 U18.4 | length 86.2
  Top Layer w5.3: R94.1@451.47,260.08 475.08,260.08 492.32,277.32 U18.4@492.32,315.56
UART/EPWM_MUX_EN: R396.1 R398.2 U54.15 U63.14 | length 304.1
  Top Layer w5.3: U54.15@2605.18,457 2605.18,487.19 2613.22,495.22 v1(2641.13,495.22) 2641.13,533 2645.36,537.23 R398.2@2671.47,537.23 2671.47,539.76 2680.63,548.92 2687.98,548.92 2697.94,558.87 2716.98,558.87 R396.1@2725.68,567.58
  Bottom Layer w5.3: U63.14@2578.49,508.67 2578.49,484.23 2584.41,478.31 2593.55,478.31 2602.04,486.81 2605.9,486.81 2614.32,495.22 v1(2641.13,495.22)
UART/EPWM_MUX_SEL: R395.1 R397.2 U54.1 U63.1 | length 724.9
  Top Layer w5.3: v1(2690.18,713.16) 2688.7,713.16 2680.72,705.18 2639.1,705.18 2632.77,698.85 2632.77,683.41 U54.1@2630.77,681.41 2630.77,621.86 2646.33,606.3 R397.2@2671.47,606.3 2680.34,615.17 R395.1@2725.69,615.17 R395.1@2729.62,615.17
  SIG 1 w5.3: v1(2471.32,816.48) 2474.76,816.48 2479.48,821.2 2649.19,821.2 2690.18,780.2 v1(2690.18,713.16)
  Bottom Layer w5.3: v1(2471.32,816.48) 2471.32,815.22 2472.96,813.58 2472.96,780.29 2496.72,756.53 2496.72,681.46 2499.75,678.43 U63.1@2499.75,658.28
USBTYPEC_CC1: J5.A5 R439.2 U18.1 U20.4 U20.7 | length 997.4
  Top Layer w5.3: v1(378.93,345.42) 382.33,345.42 394.87,357.96 394.87,366.96 R439.2@402.52,374.61 423.19,374.61 444.85,352.96 U18.1@474.61,352.96 ; U20.4@1018.85,453.43 U20.7@1018.85,420.56 1018.85,399.45 1027.76,390.54 v1(1027.76,390) 1055,390 1079.12,365.88 1079.12,312.74 J5.A5@1078.98,312.6
  SIG 1 w12: v1(378.93,345.42) 378.93,343.79 385.78,336.95 385.78,331.81 399.18,318.42 434.72,318.42 466.95,350.65 736.61,350.65 765.01,379.05 1016.82,379.05 v1(1027.76,390)
USBTYPEC_CC2: J5.B5 U18.2 U20.5 U20.6 | length 1045.9
  Top Layer w5.3: v1(408.65,341.29) 408.7,341.24 421.97,341.24 425.99,337.21 U18.2@474.61,337.21 ; J5.B5@1147.87,245.67 v1(1147.87,281.86)
  Top Layer w8: v1(978.53,405.47) 994.48,405.47 999.17,410.16 U20.5@999.17,453.43
  SIG 1 w4.75: v1(408.65,341.29) 408.65,371.62 412.09,375.06 450.73,375.06 461.46,364.33 725.24,364.33 766.42,405.5 v1(978.53,405.47)
  Bottom Layer w8: v1(978.53,405.47) 980.85,405.47 1026,360.33 1026,304.86 1049,281.86 v1(1147.87,281.86)
VBUS_TYPEC_5V0: C102.2 C103.1 D1.2 J5.A4 J5.A9 J5.B4 J5.B9 L1.1 | length 218.1
  Top Layer w11: v1(1058.97,353) 1059.13,352.84 1059.13,312.76 J5.A4@1059.29,312.6 1059.29,281.86 1069.13,272.02 J5.B9@1069.13,245.67 ; J5.B4@1167.56,245.67 1167.56,269.9 1177.4,279.74 J5.A9@1177.4,312.6 1177.4,348.15
  other v1: 1172.7,356 1137.49,385.39 1209.25,407.5 1128.42,429.5 1197.98,451
VBUS_XDS_5V0: C227.1 C231.1 J34.1 R132.2 R136.2 TP23.1 U45.1 U45.2 U45.8 | length 1755.9
  Top Layer w12: v1(430.11,1102.74) 430.11,1053.63 U45.8@430.3,1053.44
  Top Layer w15: J34.1@161.81,992.9 212.95,992.9 v1(226.14,979.71)
  SIG 1 w12: v1(430.11,1102.74) 414.87,1102.74 334.47,1183.14 308.39,1183.14 v1(275.25,1150) 275.25,1148.38 266.14,1139.26 v1(266.14,979.71) v1(226.14,979.71) 225.24,978.81 225.24,954.38 v1(224.34,953.48) 224.34,937.28 231.36,930.25 555.25,930.25 593.83,968.83 614.51,968.83 663.99,919.35 722.9,919.35 767.47,963.92 767.47,982.73 790.03,1005.29 1170.07,1005.29 1195.76,1030.99 v1(1247.27,1030.99)
  Bottom Layer w12: R136.2@275.17,1121.06 275.17,1149.93 v1(275.25,1150) ; R132.2@1225.19,1014.22 1229.03,1018.06 1234.35,1018.06 v1(1247.27,1030.99)
VDD_AM263P_1V2: C1.1 C2.1 C3.1 C19.2 C20.2 C21.2 C22.2 C29.2 C30.2 C31.2 C32.2 C39.2 C40.2 C41.2 C42.2 C44.2 C45.2 C46.2 C47.2 C49.1 C50.1 C51.1 C52.1 C53.1 C54.1 C55.1 C56.1 C157.1 C158.1 C159.1 L2.2 R153.2 TP10.1 U1.D10 U1.E9 U1.E11 U1.F9 U1.F11 U1.G5 U1.G6 U1.G13 U1.G14 U1.H3 U1.J15 U1.J16 U1.K5 U1.K6 U1.K13 U1.K14 U1.N5 U1.N6 U1.N13 U1.N14 U1.R9 U1.T4 U29.3 | length 1249.2
  Top Layer w10: U29.3@2420.33,971.21 2420.33,995.01 2426.7,1001.38
  Top Layer w15: R153.2@2432.33,783.06 2436.13,786.86 2477.26,786.86 2484.74,794.34 2500.67,794.34 v1(2501.24,794.91) ; v1(3594.38,1178.07) U1.H3@3610.13,1162.32 ; v1(3625.87,894.61) U1.T4@3641.62,910.35 ; v1(3657.37,989.09) U1.N5@3673.12,1004.84 ; v1(3657.37,1083.58) U1.K5@3673.12,1099.33 ; v1(3657.37,1209.57) U1.G5@3673.12,1193.82 ; v1(3688.87,989.09) U1.N6@3704.61,1004.84 ; v1(3688.87,1083.58) U1.K6@3704.61,1099.33 ; v1(3688.87,1209.57) U1.G6@3704.61,1193.82 ; v1(3783.35,926.1) U1.R9@3799.1,941.85 ; v1(3783.35,1241.06) U1.F9@3799.1,1225.32 ; v1(3783.35,1272.56) U1.E9@3799.1,1256.81 ; U1.D10@3830.6,1288.31 v1(3846.35,1304.06) ; U1.F11@3862.09,1225.32 v1@3876.89,1240.11 ; v1@3875,1242 3875,1243.7 3862.09,1256.61 U1.E11@3862.09,1256.81 v1(3877.84,1272.56) ; U1.N13@3925.09,1004.84 v1(3940.83,989.09) ; U1.K13@3925.09,1099.33 v1(3940.83,1083.58) ; U1.G13@3925.09,1193.82 v1(3940.83,1209.57) ; U1.N14@3956.58,1004.84 v1(3972.33,989.09) ; U1.K14@3956.58,1099.33 v1(3972.33,1083.58) ; U1.G14@3956.58,1193.82 v1(3972.33,1209.57) ; U1.J15@3988.08,1130.83 v1(4003.83,1146.57) ; U1.J16@4019.57,1130.83 v1(4035.32,1146.57)
  Bottom Layer w10: v1(3657.37,989.09) 3670.71,989.09 C56.1@3673,991.38 3675.29,989.09 v1(3688.87,989.09) ; v1(3783.35,1272.56) 3784.54,1273.75 C30.2@3802.01,1273.75 ; v1@3785.66,1239.57 C31.2@3801.86,1239.57 ; v1(3940.83,989.09) 3942.36,987.56 3946.71,987.56 3949.24,985.03 3955.68,985.03 C39.2@3956.58,984.12 ; v1(3940.83,1209.57) 3944.25,1206.15 C19.2@3956.58,1206.15 ; C39.2@3955.6,984.12 3956.5,985.03 3966.1,985.03 3970.17,989.09 v1(3972.33,989.09) ; C19.2@3956.58,1206.06 C19.2@3956.58,1206.15 ; v1(3972.33,1209.57) 3968.91,1206.15 C19.2@3956.58,1206.15
  Bottom Layer w12: 3476.56,1318.63 C49.1@3476.56,1341.5 ; C54.1@3654.78,1102.11 3654.78,1086.17 v1(3657.37,1083.58) ; v1(3657.37,1209.57) 3660.78,1206.15 C41.2@3673,1206.15 ; C41.2@3673,1206.06 C41.2@3673,1206.15 ; v1(3688.87,1083.58) 3693.17,1087.89 C46.2@3693.17,1102.11 ; v1(3688.87,1209.57) 3685.45,1206.15 C41.2@3673,1206.15 ; v1(3783.35,926.1) 3790.36,933.11 C50.1@3814.85,933.11 ; C22.2@3927.21,1115.08 3927.21,1097.2 v1(3940.83,1083.58) 3950.53,1073.89 3962.64,1073.89 v1(3972.33,1083.58) ; C55.1@4002.99,1115.08 4002.99,1145.74 v1(4003.83,1146.57)
  Bottom Layer w15: C1.1@3338.57,1012.28 v1(3338.57,1054.11) ; v1(3395.62,1295.92) 3395.84,1295.7 C44.2@3395.84,1247.05 ; C40.2@3395.84,1095.92 3395.84,1055.42 v1(3396.03,1055.23) ; C32.2@3445.84,1247.31 3445.84,1295.52 v1(3446.24,1295.92) ; v1(3445.92,1058.83) 3446.46,1059.38 C29.2@3446.46,1095.92 ; v1(3783.35,1241.06) 3784.17,1241.06 v1@3785.66,1239.57 ; v1(3877.84,1241.06) 3878.42,1241.64 3878.42,1256.6 C51.1@3879.18,1257.37 ; v1(3877.84,1272.56) 3878.42,1271.99 3878.42,1258.14 C51.1@3879.18,1257.37 ; C51.1@3879.97,1257.37 C51.1@3879.18,1257.37
  other v1: 3293.32,1052.71 2482.18,1110.22 2532.18,1110.22 2582.19,1110.22 2482.18,1160.22 2532.18,1160.22 2582.19,1160.22 2482.18,1210.22 2532.18,1210.22 2582.19,1210.22 3316.37,1288.07
VDD_ETH1_1V1_FILT: C114.1 C115.2 C116.1 C117.1 C118.1 C119.1 C120.1 C121.1 FB3.2 U22.6 U22.31 U22.39 | length 611.2
  Top Layer w10: C120.1@6779.03,729.88 v1(6810,729.88)
  Top Layer w15: FB3.2@6215.25,1311.34 6274.72,1311.34 6283.04,1319.66 6344,1319.66 6345.46,1321.12 v1(6375,1321.12) ; C119.1@6397.76,745.04 6412.91,729.88 v1(6440,729.88) 6440.57,730.46 6455.73,730.46 C118.1@6470.32,745.04 ; C116.1@6556.28,918.09 6586.71,918.09 v1(6590,921.38)
  Bottom Layer w8: C117.1@6555.72,907.76 6556.28,907.2 U22.39@6556.28,853.9
  Bottom Layer w10: v1(6440,729.88) U22.31@6491.32,729.88 ; 6556.28,886.71 6556.28,907.2 C117.1@6556.28,921.46 6589.92,921.46 v1(6590,921.38) ; U22.6@6759.03,729.88 v1(6810,729.88) C121.1@6846.59,729.88 ; 6791.84,729.88 6826.59,729.88
  other v1: 6397.76,1290.74 6420,1321.12
VDD_ETH1_2V5_FILT: C122.1 C123.2 C124.1 C125.1 C126.1 C127.1 FB4.2 U22.3 U22.9 | length 1183.3
  Top Layer w10: 6315,963.52 6426.67,851.86 6751.7,851.86 6779.03,824.52 C126.1@6779.03,788.94 v1(6810,788.94) 6840,758.94 6840,700.83 v1(6810,670.83) C124.1@6779.03,670.83
  Top Layer w15: FB4.2@6142.49,970.9 6208.74,970.9 C122.1@6210,972.16 6218.63,963.52 6280.09,963.52 6315,963.52
  Bottom Layer w10: U22.9@6759.03,670.83 6791.84,670.83 ; U22.3@6759.03,788.94 v1(6810,788.94) C127.1@6846.59,788.94 ; 6791.84,788.94 6826.59,788.94 ; 6826.59,670.83 6791.84,670.83 ; C125.1@6846.59,670.83 v1(6810,670.83) 6791.84,670.83
VDD_ETH2_1V1_FILT: C191.1 C192.2 C193.1 C194.1 C195.1 C196.1 C197.1 C198.1 FB5.2 U37.6 U37.31 U37.39 | length 555.6
  Top Layer w10: C197.1@6775.03,1679.88 v1(6810,1679.88)
  Top Layer w15: FB5.2@6215.25,1449.44 6274.72,1449.44 C191.1@6279,1453.72 6283.04,1457.76 6344,1457.76 6345.46,1459.22 v1(6375,1459.22) ; C196.1@6402.76,1695.04 6417.91,1679.88 v1(6440,1679.88) 6458.71,1679.88 C195.1@6475.32,1696.49 ; C193.1@6556.28,1868.09 6586.71,1868.09 v1(6590,1871.38)
  Bottom Layer w9: v1(6440,1679.88) U37.31@6491.32,1679.88 ; U37.39@6556.28,1803.9 C194.1@6556.28,1867.12 ; U37.6@6759.03,1679.88 v1(6810,1679.88)
  Bottom Layer w10: C194.1@6556.17,1867.23 C194.1@6556.28,1867.12 ; C194.1@6556.28,1871.46 6589.92,1871.46 v1(6590,1871.38) ; v1(6810,1679.88) C198.1@6846.59,1679.88
  other v1: 6396.3,1442.33 6418.08,1459.11
VDD_ETH2_2V5_FILT: C199.1 C200.2 C201.1 C202.1 C203.1 C204.1 FB6.2 U37.3 U37.9 | length 1263
  Top Layer w10: FB6.2@6215.25,1188.64 6278.76,1188.64 C199.1@6278.93,1188.47 6300,1188.47 6309.86,1178.61 6334,1178.61 6374.64,1178.61 6375,1178.25 6432.19,1235.44 6538.39,1235.44 6674.39,1371.44 6674.39,1499.1 6734.47,1559.19 6785.59,1559.19 6810,1583.6 v1(6810,1620.83) ; C203.1@6775.03,1738.94 v1(6810,1738.94) 6840,1708.94 6840,1650.83 v1(6810,1620.83) ; C201.1@6779.03,1620.83 v1(6810,1620.83)
  Bottom Layer w9: U37.9@6759.03,1620.83 v1(6810,1620.83) ; U37.3@6759.03,1738.94 v1(6810,1738.94)
  Bottom Layer w10: v1(6810,1620.83) C202.1@6846.59,1620.83 ; v1(6810,1738.94) C204.1@6846.59,1738.94
VDD_ETH_1V1: C175.2 C176.1 FB3.1 FB5.1 R159.2 TP11.1 U31.9 U31.10 | length 247.4
  Top Layer w10: U31.9@5854.25,1567.31 5883.12,1567.31 5890,1574.19 ; U31.10@5854.25,1586.99 5882.39,1586.99 5909.13,1613.73 C176.1@5909.13,1617.67
  Top Layer w15: FB3.1@6162.1,1310.55 FB5.1@6162.1,1449.44
VDD_ETH_2V5: C164.2 C165.1 FB4.1 FB6.1 R151.2 TP12.1 U30.9 U30.10 | length 150.9
  Top Layer w10: 5847,1207.18 5847,1175.05 U30.10@5854.25,1167.8 5882.39,1167.8 5909.13,1194.55 C165.1@5909.13,1198.48 ; U30.9@5854.25,1148.12 5883.12,1148.12 5890,1155
VDD_XDS3V3: C139.2 C140.2 C141.2 C145.2 C146.2 C147.2 C148.2 C149.2 C150.2 C228.2 C232.2 C233.2 C250.1 C251.1 R138.2 R139.2 R140.2 R141.2 R142.2 R143.2 R144.2 R251.2 R301.1 R311.2 R312.2 R336.1 R337.1 R338.1 R339.1 R340.1 R341.1 R399.2 R400.2 R405.2 TP25.1 U24.7 U24.8 U24.16 U24.26 U24.28 U24.39 U24.47 U24.51 U24.52 U24.69 U24.79 U24.90 U24.101 U24.113 U24.122 U25.1 U26.8 U27.8 U45.3 U45.4 U56.1 U58.1 U59.1 | length 3007.5
  Top Layer w7: U45.3@481.48,943.2 481.29,943.01 481.29,926.06 492.56,914.8 493.85,914.8 ; C141.2@1217.76,1733.64 1219.59,1735.47 U25.1@1290.47,1735.47
  Top Layer w8: TP25.1@809.21,1094.23 809.21,1093.72 829.81,1073.12 835.39,1073.12 v1(837.3,1071.21)
  Top Layer w12: R144.2@375.63,1204.12 375.63,1181.32 v1(389.15,1167.8) ; C145.2@518.94,1188.47 v1(550,1188.47) ; v1(540,1474.52) 539.64,1474.16 507.96,1474.16 500.19,1481.93 500.19,1505.66 C150.2@504.12,1505.66 504.62,1505.16 543.17,1505.16 v1(543.66,1504.67) ; R251.2@631.97,1238.85 v1(631.97,1272.33) ; v1(646.08,973.57) 660,987.49 C232.2@660,1020.15 ; v1(771.61,1079.26) 771.61,1077.63 781.82,1067.43 781.82,1050.65 C147.2@787.63,1044.84 ; R400.2@809.19,1490 809.19,1456.89 v1(811.08,1455) ; v1(1206.01,1696.73) 1217.76,1708.48 C141.2@1217.76,1733.64 ; v1(1233.33,1347.16) 1232.18,1348.31 1232.18,1370.47 1226.37,1376.28 C140.2@1224.21,1376.28 1224.32,1376.39 1287.25,1376.39 U26.8@1287.35,1376.5 ; v1(1235.44,1116.58) 1216.66,1135.36 C139.2@1216.66,1165.27 U27.8@1286.73,1165.27
  Top Layer w15: U58.1@260.25,1603.6 260.05,1603.4 260.05,1506.47 C250.1@259.85,1506.27 259.85,1459.6 281.95,1437.5 v1(302.21,1437.5) ; v1(665.14,1088.76) 674.39,1098.01 C228.2@674.39,1124.76 ; v1(673.66,1572.4) 673.66,1573.21 681.33,1580.88 R311.2@681.33,1607.83 ; R312.2@688.16,1499.3 688.16,1497.34 690.51,1494.99 704.32,1494.99 v1@715.7,1483.61 ; v1@719.19,1487.09 727.14,1495.05 R399.2@754.13,1495.05 804.88,1495.05 805.2,1495.36 R400.2@805.2,1496.8 ; v1(848.81,1470.18) C148.2@848.81,1497.94 ; v1(856.9,1297.63) 857.71,1297.63 858.78,1296.56 R338.1@896.06,1296.56 ; v1(859.36,1383.25) 860.18,1383.25 863.58,1386.65 891.75,1386.65 R341.1@896.06,1390.96 ; v1(861.32,1249.98) 861.89,1249.41 894.71,1249.41 R336.1@896.06,1248.06 ; v1(862.52,1338.19) 863.09,1338.76 894.3,1338.76 R337.1@896.06,1340.53 ; v1(870.05,977.12) 904.69,1011.75 R405.2@936.92,1011.75 ; v1(870.47,1437.81) R301.1@896.06,1437.81 ; v1(893.24,1554.59) 893.81,1554.02 893.81,1533.09 R339.1@896.06,1530.84 R340.1@896.06,1481.93 ; v1(1030.86,1380.88) 1087.35,1380.88 1088.37,1379.86 1097.29,1379.86 C149.2@1098.65,1378.5
  Bottom Layer w7: U24.7@492.35,1174.76 536.3,1174.76 v1(550,1188.47) 547.96,1190.51 U24.8@492.35,1190.51 ; U24.16@492.35,1316.5 v1@539.81,1316.5 ; U24.26@492.35,1473.98 492.52,1474.14 539.62,1474.14 v1(540,1474.52) ; U24.28@492.35,1505.47 492.52,1505.31 543.02,1505.31 v1(543.66,1504.67) ; v1@645.89,973.76 U24.122@645.89,1021.22 ; U24.39@645.89,1627.52 646.06,1627.35 646.06,1598.5 672.16,1572.4 v1(673.66,1572.4) ; U24.47@771.88,1627.52 771.88,1593.48 780.62,1584.74 v1(780.62,1584.3) ; U24.113@787.63,1021.22 787.63,1063.24 ; U24.51@834.87,1627.52 835.04,1627.69 835.04,1653.41 839.41,1657.78 846.08,1657.78 850.45,1653.41 850.45,1627.69 850.79,1627.35 850.79,1597.93 893.24,1555.48 v1(893.24,1554.59) ; v1(1049.22,1205.81) 1049.23,1186.13 1060.59,1174.76 U24.90@1098.65,1174.76 ; U24.79@1098.65,1347.99 1098.82,1347.82 1127.67,1347.82 1128.42,1347.08 1137.49,1338 1156.89,1338 1166.88,1347.99 1193.21,1347.99 C251.1@1197.04,1344.17 1200.03,1347.16 1236.31,1347.16 1243.47,1340 U59.1@1286.89,1340 ; U24.69@1098.65,1505.47 1135.19,1505.47 1140.86,1499.8 v1(1143.84,1499.8)
  Bottom Layer w8: v1@539.81,1316.5 v1(540,1316.68) ; v1@645.89,973.76 v1(646.08,973.57) ; v1(771.61,1079.26) 787.63,1063.24 ; v1(908.85,942.03) 909.03,942.22 C146.2@938.26,942.22 ; U24.101@976.6,1021.22 976.6,968.06 989.03,955.63 989.03,952.19 997,944.23 v1(997,942.5)
  Bottom Layer w12: v1(963.57,1744.5) 963.63,1744.44 R141.2@992.24,1744.37 R141.2@992.24,1744.37 R140.2@1039.13,1744.37 ; R139.2@1093.35,1744.37 1122.36,1744.37 1131.6,1735.13 v1(1133.22,1735.13) ; v1(1206.01,1696.73) 1206.66,1696.08 1206.66,1657.04 R138.2@1207.31,1656.39 ; U56.1@1291.46,1573.33 v1@1338.42,1573.33
  Bottom Layer w15: v1(870.05,977.12) 870.63,976.54 874.34,976.54 v1(908.85,942.03) ; v1@996.86,942.36 v1(997,942.5) ; R143.2@1211.05,1476.93 R142.2@1211.05,1514.93 1212.84,1516.72 1235.59,1516.72 v1(1236.17,1517.3)
  other v1: 606.84,917.37 607.1,943.18 717.77,1484.06 1338.45,1573.29
VDDA18_AM263P_OSC_PLL: C38.1 FB2.2 U1.R4 | length 630.9
  Top Layer w10: v1(3625.87,926.1) U1.R4@3641.62,941.85
  SIG 1 w5: 3609.88,885.13 3609.88,910.11 v1(3625.87,926.1)
  SIG 1 w8: 3607.6,841.79 3609.88,844.07 3609.88,885.13
  SIG 1 w15: v1(3500,605) 3500,639.55 3511.53,651.08 3511.53,684.82 3560.5,733.79 3587.94,733.79 3611.05,756.9 3611.05,806.77 3601.95,815.87 3600.3,817.51 3600.3,834.5 3607.6,841.79
  Bottom Layer w15: v1(3500,605) 3500,491.86 3505.84,486.02 C38.1@3531.39,486.02 3532.41,485 FB2.2@3594.44,485
VDDA_AM263P_1V8_LDO: C33.1 C34.1 C35.1 C36.1 C37.1 FB2.1 R189.2 S1.1 U1.R6 U1.R8 U1.R11 | length 1732.4
  Top Layer w15: v1(3688.87,926.1) U1.R6@3704.61,941.85 ; v1(3751.86,926.1) U1.R8@3767.61,941.85 ; U1.R11@3862.09,941.85 v1(3877.84,926.1)
  Top Layer w20: S1.1@3093,561.06 v1(3093,627.88) ; R189.2@3586.2,697.45 3586.2,695.79 3586.36,695.63 3595.42,695.63 v1(3605.81,685.24)
  SIG 1 w5: v1(3688.87,926.1) 3704.61,941.85 3767.61,941.85 ; 3698.11,869.25 3704.49,875.62 3704.49,910.48 ; v1(3751.86,926.1) 3767.61,941.85 ; 3988.08,941.85 3893.59,941.85 v1(3877.84,926.1) 3862.09,941.85 3767.61,941.85
  SIG 1 w5.5: v1(3688.87,926.1) 3704.49,910.48
  SIG 1 w20: v1(3093,627.88) 3131.36,666.24 3412.98,666.24 3424.7,654.52 3424.7,575.28 3488.08,511.9 3494.42,511.9 3494.66,511.66 3629.74,511.66 3677.43,559.36 3677.43,608.39 v1(3678.01,608.97) ; v1(3678.01,663.97) 3678.01,850.65 3697.36,870
  Bottom Layer w12: v1@3676.49,708.97 C36.1@3712.76,708.97 ; v1(3678.01,663.97) 3683.01,658.97 C34.1@3712.76,658.97
  Bottom Layer w20: v1(3678.01,608.97) 3698.15,608.97 3707.39,599.73 C33.1@3707.39,569.08 ; v1(4104.69,740.75) C35.1@4139.44,740.75
  other v1: 3676.01,708.97
VDDA_AM263P_3V3: C25.1 C26.1 C27.1 C28.1 FB1.2 U1.P7 U1.P9 U1.P11 | length 165.1
  Top Layer w15: v1(3720.36,957.6) U1.P7@3736.11,973.35 ; v1(3783.35,957.6) U1.P9@3799.1,973.35 ; U1.P11@3862.09,973.35 v1(3877.84,957.6)
  Bottom Layer w12: C26.1@3898.93,608.97 v1(3931.68,608.97) ; C27.1@3898.93,658.97 v1(3931.68,658.97) ; C28.1@3898.93,708.97 v1(3931.68,708.97)
VDDA_ETH1_1V8: TP7.1 U22.13 U22.48 | length 622.8
  Top Layer w12: TP7.1@6700.57,611.5 6700.82,611.24 6700.82,592.62 v1(6733.44,560) 6800.59,560 6870,629.41 6870,806.84 6795.28,881.56 v1(6762.73,881.56)
  Bottom Layer w8: U22.13@6733.44,586.18 6733.44,563.47 v1@6734.74,562.17
  Bottom Layer w12: U22.48@6733.44,853.9 6733.44,873.44 6741.56,881.56 v1(6762.73,881.56)
VDDA_ETH2_1V8: TP19.1 U37.13 U37.48 | length 589.7
  Top Layer w12: v1(6729.08,1494.18) 6748.82,1513.91 TP19.1@6779.03,1513.91 6811.27,1513.91 6875,1577.64 6875,1757.84 6812.36,1820.48 v1(6760.22,1820.48)
  Bottom Layer w8: v1@6729.57,1497.3 6729.57,1497.36 6733.44,1501.24 U37.13@6733.44,1536.18 ; U37.48@6733.44,1803.9 6733.44,1819.71 6738.13,1824.39 6753.6,1824.39 6757.52,1820.48 v1(6760.22,1820.48)
  Bottom Layer w12: v1(6729.08,1494.18) v1@6729.08,1495.8
VDDC_XDS_1V0: C153.2 C154.2 C155.2 C156.2 U24.87 U24.115 | length 932.1
  Top Layer w12: v1(706.78,942.22) 707.93,943.37 707.93,961.21 740.38,993.66 C155.2@740.38,997.6
  Top Layer w15: v1(1054.53,1241.42) 1055,1240.95 1055,1232.82 1058.13,1229.69 1059.45,1229.69 1063.25,1225.89 1077.07,1225.89 C153.2@1081.38,1221.57 1081.38,1260.16 1089.25,1268.03 C156.2@1089.25,1270
  SIG 1 w12: v1(706.78,942.22) 707.59,943.03 707.59,955.6 779.46,1027.47 995.06,1027.47 1075.56,1107.97 1075.56,1219.85 1054.53,1240.88 v1(1054.53,1241.42)
  Bottom Layer w7: 748.48,973 756.13,980.65 U24.115@756.13,1021.22 ; v1(1054.53,1241.42) 1056.57,1239.38 1056.57,1233.03 1067.59,1222.01 U24.87@1098.65,1222.01
  Bottom Layer w12: v1(706.78,942.22) 706.97,942.04 751.17,942.04 C154.2@751.36,941.85 748.48,944.73 748.48,973
VDDS_AM263P_LDO_1V8: C14.1 C15.1 C16.1 C17.1 C18.1 C98.1 U1.D6 U1.E15 U1.L4 U1.N15 U1.T3 | length 1026.9
  Top Layer w15: v1(3594.38,894.61) U1.T3@3610.13,910.35 ; v1(3625.87,1052.09) U1.L4@3641.62,1067.84 ; v1(3688.87,1304.06) U1.D6@3704.61,1288.31 ; U1.N15@3988.08,1004.84 v1(4003.83,989.09) ; U1.E15@3988.08,1256.81 v1(4003.83,1272.56)
  SIG 1 w4: v1(3688.87,1304.06) 3705,1320.19 3705,1352.62
  SIG 1 w4.75: v1(4003.83,1272.56) 4019.57,1256.82 4046.43,1256.82 4049.19,1254.06 ; 4019.95,1005.22 4102.59,1005.22 4109.9,1012.53 4114.06,1012.53
  SIG 1 w12: v1(4003.83,989.09) 4019.95,1005.22 ; 4049.19,1254.06 v1(4129.81,1254.06) ; 4114.06,1012.53 4127.88,1012.53 v1(4129.02,1013.68)
  SIG 1 w15: v1(3550.2,800.12) 3550.78,800.69 3550.78,821.4 3557.88,828.51 3557.88,858.11 v1(3594.38,894.61) ; v1(3688.87,1443.54) 3705,1427.4 3705,1352.62
  Bottom Layer w15: v1(3550.2,800.12) 3550.78,799.54 3550.78,770.22 C15.1@3553.63,767.37 ; v1(3688.87,1443.54) C16.1@3688.87,1476.28
  Bottom Layer w20: v1(4129.02,1013.68) 4129.38,1013.32 C17.1@4167.23,1013.32 4167.23,1249.74 4162.92,1254.06 C18.1@4162.56,1254.06 v1(4129.81,1254.06)
VPP_AM263P_1V7: C255.2 C256.1 R190.2 R360.2 R362.2 TP33.1 U55.1 | length 1920.9
  Top Layer w15: v1(3145.44,762.66) 3145.44,722.88 3204.15,664.16 3204.15,567.38 3212.94,558.59 3395.53,558.59 3449.69,612.75 3449.69,688.66 3458.48,697.45 R190.2@3535,697.45
  SIG 1 w15: v1(3089.05,867.26) 3089.05,819.04 v1(3145.44,762.66)
  Bottom Layer w10: U55.1@3118.65,1643.59 3140.03,1643.59 3161.17,1664.74 3161.17,1681.51 C255.2@3164.05,1684.38
  Bottom Layer w15: v1(3089.05,867.26) 3089.05,983.72 2996.48,1076.29 2996.48,1099.12 3009.93,1112.58 3009.93,1175.59 2984.21,1201.32 2984.21,1412.99 3018.84,1447.62 3045.57,1447.62 3123.92,1525.97 3186.15,1525.97 3259.91,1599.73 3259.91,1668.64 3246.24,1682.31 R362.2@3223.04,1682.31
VPP_LDO_EN: R364.2 U55.4 U63.13 | length 2420.8
  Top Layer w5.3: v1(2245.22,468.12) 2245.71,467.63 2259.06,467.63 2308.93,517.5 2308.93,558.44 2307.38,559.99 2300.47,566.9 2300.47,626.55 v1(2259.12,667.89)
  Bottom Layer w5.3: v1(2245.22,468.12) 2313.52,468.12 2321.85,459.79 2379.87,459.79 2448.62,391.04 2543.94,391.04 2557.67,377.3 2628.04,377.3 2703.34,452.6 2703.34,528.77 2703.59,529.02 2703.59,535.8 v1@2704.29,536.5 ; v1(2259.12,667.89) 2259.12,711.91 2419.59,872.38 2566.97,872.38 2583.38,888.78 2583.38,1047.19 2631.61,1095.42 2631.61,1172.76 2653.6,1194.75 2653.6,1293.95 2660.76,1301.11 2680.27,1301.11 2695.24,1316.08 2842.56,1316.08 3042.63,1516.14 R364.2@3042.63,1550.16 3041.88,1550.91 U55.4@3041.88,1592.41 ; U63.13@2598.18,508.67 2616.36,508.67 2625.31,517.62 2675.5,517.62 2694.94,537.06 2703.74,537.06 v1(2706.02,539.35)
VSD_3V3: C67.1 C71.2 J2.4 U8.5 U8.6 U10.1 U11.10 | length 498.8
  Top Layer w10: v1(235,633.9) U10.1@263.65,633.9
  Top Layer w12: U11.10@523.63,620 553.44,620 569.16,604.28
  Top Layer w15: 569.16,604.28 569.16,614.57 584.83,630.23 600.07,630.23 C67.1@611.03,641.19 ; 569.16,612.85 572.43,609.58 572.43,593.76 v1(573.01,593.18) ; v1(612.25,593.18) 612.25,594 611.03,595.22 C67.1@611.03,641.19 ; 650,667.85 660.75,678.6 U8.5@686.89,678.6 ; U8.6@686.89,641.19 C67.1@611.03,641.19
  Bottom Layer w12: v1(532.67,785.81) 567.73,785.81 568.11,785.43 568.11,766.13 547.13,745.14 547.13,723.87 566.06,704.93 J2.4@566.06,669.61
